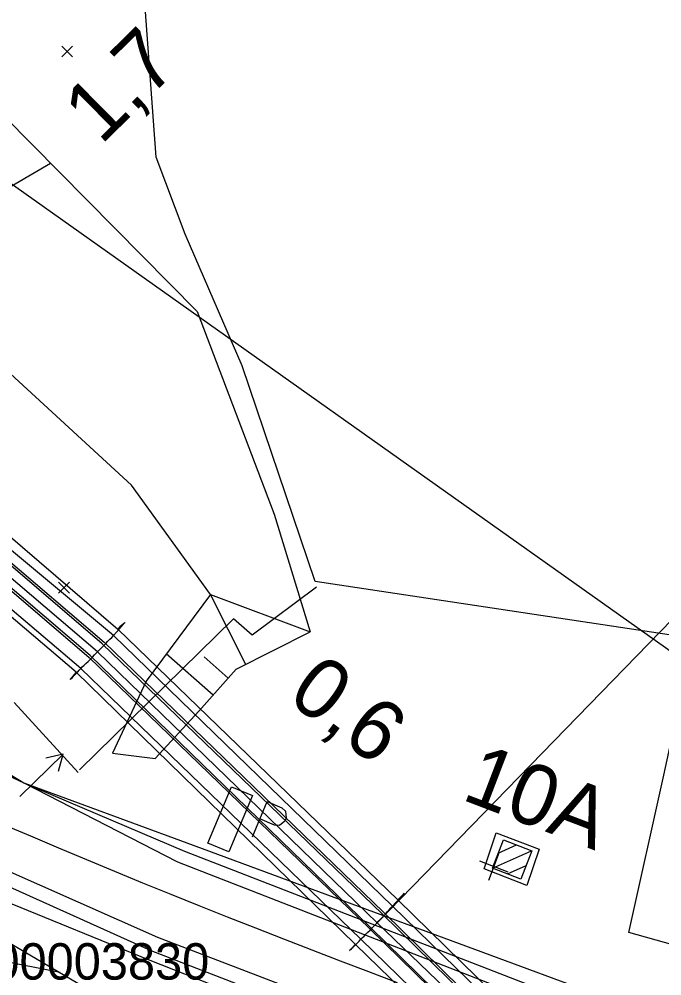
# Model space of a CAD drawing. Extents: x -800194 to -799078, y -1007177 to -1006597.
# Drawn here: x -799766.47 to -799745.3, y -1006976.93 to -1006945.41 of the extents above; entities that cross this region are included whole.
import ezdxf

# ---------------------------------------------------------------- set-up
doc = ezdxf.new("R2010")
doc.units = 0
for name, color, linetype in [('02_Osa_koleje', 7, 'Continuous'), ('Vrstva 11', 7, 'Continuous'), ('Vrstva 12', 7, 'Continuous'), ('Vrstva 13', 7, 'Continuous'), ('Vrstva 16', 7, 'Continuous'), ('Vrstva 17', 7, 'Continuous'), ('Vrstva 18', 7, 'Continuous'), ('Vrstva 36', 7, 'Continuous'), ('Vrstva 4', 7, 'Continuous'), ('Vrstva 48', 7, 'Continuous'), ('Vrstva 49', 7, 'Continuous'), ('Vrstva 55', 7, 'Continuous'), ('Vrstva 60', 7, 'Continuous'), ('Vrstva 63', 7, 'Continuous'), ('Vrstva 7', 7, 'Continuous')]:
    doc.layers.add(name, color=color, linetype=linetype)

msp = doc.modelspace()

# ---------------------------------------------------------------- linework, layer by layer
at = {"layer": '02_Osa_koleje'}
msp.add_lwpolyline([(-799770.682, -1006970.328), (-799769.768, -1006970.733), (-799768.852, -1006971.134), (-799767.934, -1006971.532), (-799767.016, -1006971.927), (-799766.096, -1006972.319), (-799765.175, -1006972.709), (-799764.252, -1006973.095), (-799763.329, -1006973.478), (-799762.404, -1006973.858), (-799761.478, -1006974.235), (-799760.55, -1006974.609), (-799759.621, -1006974.98), (-799758.692, -1006975.348), (-799757.761, -1006975.713), (-799756.828, -1006976.075), (-799755.895, -1006976.434), (-799754.96, -1006976.789), (-799754.025, -1006977.142)], dxfattribs=at)
at = {"layer": 'Vrstva 11'}
for p, q in [((-799750.69, -1006972.883), (-799750.087, -1006972.614)), ((-799750.88, -1006973.378), (-799749.592, -1006972.804)), ((-799750.389, -1006973.57), (-799749.778, -1006973.297))]:
    msp.add_line(p, q, dxfattribs=at)
msp.add_lwpolyline([(-799750.523, -1006972.447), (-799749.589, -1006972.805), (-799749.947, -1006973.739), (-799750.881, -1006973.381)], close=True, dxfattribs=at)
at = {"layer": 'Vrstva 12'}
msp.add_lwpolyline([(-799751.16, -1006973.407), (-799750.766, -1006972.211), (-799749.342, -1006972.749), (-799749.756, -1006973.956), (-799751.16, -1006973.407)], dxfattribs=at)
at = {"layer": 'Vrstva 13'}
msp.add_line((-799766.453, -1006971.023), (-799765.026, -1006969.623), dxfattribs=at)
msp.add_lwpolyline([(-799765.172, -1006970.187), (-799765.026, -1006969.623), (-799765.593, -1006969.759)], dxfattribs=at)
at = {"layer": 'Vrstva 16'}
for points in [[(-799726.857, -1006999.659), (-799736.574, -1006991.623), (-799742.439, -1006986.725), (-799754.518, -1006974.879), (-799763.734, -1006965.993), (-799777.293, -1006954.374), (-799779.945, -1006952.099), (-799783.722, -1006948.693)], [(-799783.708, -1006948.669), (-799779.9, -1006952.065), (-799777.252, -1006954.333), (-799763.672, -1006965.935), (-799754.476, -1006974.829), (-799742.393, -1006986.703), (-799736.524, -1006991.578), (-799726.778, -1006999.642)], [(-799784.356, -1006949.5), (-799780.347, -1006952.62), (-799777.716, -1006954.827), (-799764.168, -1006966.436), (-799754.935, -1006975.363), (-799742.857, -1006987.188), (-799736.94, -1006992.081), (-799727.324, -1007000.028)], [(-799727.258, -1006999.988), (-799736.887, -1006992.032), (-799742.859, -1006987.132), (-799754.894, -1006975.337), (-799764.135, -1006966.374), (-799777.698, -1006954.783), (-799780.331, -1006952.581), (-799784.321, -1006949.462)], [(-799779.465, -1006951.506), (-799778.251, -1006952.583), (-799776.738, -1006953.884), (-799763.224, -1006965.504), (-799753.999, -1006974.421), (-799741.964, -1006986.204), (-799736.168, -1006991.012), (-799728.577, -1006997.215), (-799726.123, -1006999.163)], [(-799727.952, -1007000.326), (-799729.82, -1006998.717), (-799737.37, -1006992.486), (-799743.358, -1006987.594), (-799755.401, -1006975.883), (-799764.592, -1006966.926), (-799778.073, -1006955.449), (-799779.598, -1006954.142), (-799780.843, -1006953.125)]]:
    msp.add_lwpolyline(points, dxfattribs=at)
at = {"layer": 'Vrstva 17'}
msp.add_line((-799766.63, -1006967.927), (-799764.528, -1006970.233), dxfattribs=at)
for points in [[(-799756.721, -1006963.941), (-799759.125, -1006956.836), (-799761.008, -1006952.49), (-799761.962, -1006949.962), (-799762.434, -1006943.507)], [(-799756.678, -1006964.125), (-799758.792, -1006965.704), (-799759.415, -1006965.167), (-799764.485, -1006970.145)], [(-799726.806, -1006975.491), (-799728.174, -1006980.607), (-799746.39, -1006975.498), (-799745.242, -1006970.318), (-799744.263, -1006965.815), (-799756.721, -1006963.941)]]:
    msp.add_lwpolyline(points, dxfattribs=at)
at = {"layer": 'Vrstva 18'}
msp.add_line((-799754.68, -1006975.182), (-799715.262, -1006934.616), dxfattribs=at)
for points in [[(-799776.738, -1006953.884), (-799763.224, -1006965.504), (-799753.999, -1006974.421), (-799741.964, -1006986.204), (-799736.168, -1006991.012)], [(-799728.689, -1006997.417), (-799736.272, -1006991.186), (-799742.111, -1006986.385), (-799754.178, -1006974.631), (-799763.368, -1006965.72), (-799777.061, -1006954.31)], [(-799736.701, -1006991.694), (-799742.573, -1006986.82), (-799754.68, -1006975.182), (-799763.887, -1006966.256), (-799777.391, -1006954.732)], [(-799737.37, -1006992.486), (-799743.358, -1006987.594), (-799755.401, -1006975.883), (-799764.592, -1006966.926), (-799778.073, -1006955.449)], [(-799729.664, -1006998.596), (-799737.245, -1006992.341), (-799743.186, -1006987.438), (-799755.222, -1006975.72), (-799764.444, -1006966.802), (-799777.959, -1006955.323)]]:
    msp.add_lwpolyline(points, dxfattribs=at)
for centre, major_axis, ratio, start_param, end_param in [((-799764.209, -1006966.632), (1.225, 1.347), 0.00569, 5.462132, 6.45682), ((-799764.267, -1006966.931), (1.309, 1.64), 0.066438, 0.193143, 0.570602), ((-799763.899, -1006966.226), (0.719, 0.725), 0.028964, 3.823595, 5.514697), ((-799763.469, -1006965.755), (-1.321, -1.405), 0.014987, 5.711575, 6.53997), ((-799763.588, -1006965.716), (-1.214, -1.448), 0.032329, 0.280391, 0.750862), ((-799755.015, -1006975.474), (1.23, 1.269), 0.011168, 5.449588, 6.468473), ((-799755.131, -1006975.736), (1.35, 1.533), 0.01765, 0.183735, 0.556082), ((-799754.712, -1006975.133), (0.699, 0.732), 0.056068, 3.837002, 5.520083), ((-799754.595, -1006974.816), (0.979, 1.241), 0.059951, 3.363928, 3.944453), ((-799754.422, -1006974.757), (-1.164, -1.342), 0.001186, 5.709743, 6.582824)]:
    msp.add_ellipse(centre, major_axis=major_axis, ratio=ratio, start_param=start_param, end_param=end_param, dxfattribs=at)
at = {"layer": 'Vrstva 36'}
msp.add_lwpolyline([(-799759.474, -1006970.701), (-799758.787, -1006970.989), (-799759.566, -1006972.847), (-799760.253, -1006972.559)], close=True, dxfattribs=at)
msp.add_lwpolyline([(-799758.789, -1006972.343), (-799758.304, -1006971.186), (-799757.823, -1006971.388), (-799757.698, -1006971.497), (-799757.674, -1006971.727), (-799757.717, -1006971.829), (-799757.899, -1006971.978), (-799758.062, -1006971.959), (-799758.543, -1006971.757)], dxfattribs=at)
at = {"layer": 'Vrstva 4'}
for points in [[(-799766.319, -1006970.565), (-799760.949, -1006972.542), (-799747.638, -1006977.46), (-799730.549, -1006982.982), (-799710.066, -1006987.578), (-799704.728, -1006988.346), (-799693.001, -1006990.373), (-799682.434, -1006991.64), (-799671.27, -1006992.619), (-799659.31, -1006993.026), (-799648.69, -1006993.125), (-799637.398, -1006992.704), (-799625.913, -1006992.175), (-799614.965, -1006990.831), (-799603.911, -1006989.312), (-799592.728, -1006987.172), (-799581.605, -1006984.547), (-799570.583, -1006981.598), (-799559.909, -1006978.216), (-799542.956, -1006972.25), (-799531.79, -1006967.658), (-799521.285, -1006962.191), (-799511.236, -1006957.129)], [(-799779.678, -1006964.304), (-799766.319, -1006970.565), (-799761.253, -1006973.176), (-799747.77, -1006978.421), (-799730.774, -1006983.8), (-799710.333, -1006988.709), (-799704.916, -1006989.741), (-799693.131, -1006991.407), (-799682.585, -1006992.929), (-799671.325, -1006993.879), (-799659.363, -1006994.45), (-799648.66, -1006994.501), (-799637.23, -1006994.127), (-799626.066, -1006993.335), (-799614.788, -1006992.17), (-799603.669, -1006990.506), (-799592.467, -1006988.452), (-799581.281, -1006985.916), (-799570.22, -1006982.998), (-799559.296, -1006979.606), (-799542.375, -1006973.485), (-799531.236, -1006968.774), (-799520.48, -1006963.762), (-799510.394, -1006958.536)], [(-799776.864, -1006969.085), (-799770.965, -1006971.646), (-799761.91, -1006975.649), (-799748.544, -1006980.777), (-799731.457, -1006986.215), (-799711.132, -1006991.054), (-799705.482, -1006992.16), (-799693.53, -1006994.084), (-799682.801, -1006995.384), (-799671.514, -1006996.319), (-799659.449, -1006996.851), (-799648.588, -1006996.949), (-799637.262, -1006996.573), (-799625.835, -1006995.773), (-799614.546, -1006994.586), (-799603.199, -1006992.945), (-799591.969, -1006990.857), (-799580.647, -1006988.335), (-799569.534, -1006985.311), (-799558.557, -1006981.947), (-799541.405, -1006975.739), (-799530.263, -1006971.071), (-799519.455, -1006966), (-799509.248, -1006960.724)], [(-799776.864, -1006969.085), (-799771.262, -1006971.982), (-799762.131, -1006976.093), (-799748.706, -1006981.286), (-799731.51, -1006986.353), (-799711.222, -1006991.459), (-799705.527, -1006992.587), (-799693.582, -1006994.543), (-799682.85, -1006995.904), (-799671.5, -1006996.805), (-799659.556, -1006997.356), (-799648.616, -1006997.341), (-799637.276, -1006997.071), (-799625.828, -1006996.297), (-799614.43, -1006995.109), (-799603.18, -1006993.475), (-799591.849, -1006991.264), (-799580.564, -1006988.698), (-799569.449, -1006985.746), (-799558.385, -1006982.386), (-799541.268, -1006976.227), (-799530.102, -1006971.505), (-799519.398, -1006966.36), (-799509.087, -1006961.127)], [(-799779.011, -1006963.023), (-799770.632, -1006967.944), (-799766.319, -1006970.565), (-799761.021, -1006972.82), (-799747.748, -1006977.966), (-799730.719, -1006983.271), (-799710.195, -1006988.108), (-799704.765, -1006989.181), (-799693.072, -1006990.965), (-799682.554, -1006992.238), (-799671.266, -1006993.222), (-799659.388, -1006993.765), (-799648.658, -1006993.824), (-799637.385, -1006993.531), (-799625.769, -1006992.728), (-799614.9, -1006991.542), (-799603.91, -1006989.963), (-799592.572, -1006987.892), (-799581.421, -1006985.419), (-799570.327, -1006982.332), (-799559.429, -1006979.066), (-799542.601, -1006973.013), (-799531.454, -1006968.25), (-799520.744, -1006963.214)], [(-799776.864, -1006969.085), (-799771.693, -1006972.522), (-799762.217, -1006976.394), (-799748.898, -1006981.647), (-799733.68, -1006986.66), (-799728.795, -1006987.945), (-799711.349, -1006992.599), (-799705.744, -1006994.116), (-799693.689, -1006996.09), (-799689.347, -1006996.226), (-799688.222, -1006996.296), (-799683.105, -1006997.407), (-799671.667, -1006998.275)]]:
    msp.add_lwpolyline(points, dxfattribs=at)
at = {"layer": 'Vrstva 48'}
for p, q in [((-799770.541, -1006953.137), (-799765.435, -1006950.154)), ((-799759.008, -1006966.666), (-799760.173, -1006964.364)), ((-799760.084, -1006967.683), (-799761.624, -1006966.32)), ((-799759.587, -1006967.122), (-799760.381, -1006966.419))]:
    msp.add_line(p, q, dxfattribs=at)
at = {"layer": 'Vrstva 49'}
for p, q in [((-799765.068, -1006946.299), (-799764.714, -1006946.653)), ((-799765.068, -1006946.653), (-799764.714, -1006946.299)), ((-799765.172, -1006963.963), (-799764.818, -1006964.317)), ((-799765.172, -1006964.317), (-799764.818, -1006963.963)), ((-799760.173, -1006964.364), (-799756.886, -1006965.592))]:
    msp.add_line(p, q, dxfattribs=at)
for points in [[(-799777.554, -1006942.387), (-799773.745, -1006944.786), (-799766.953, -1006948.615), (-799760.613, -1006955.042), (-799758.076, -1006961.72), (-799756.886, -1006965.592)], [(-799760.173, -1006964.364), (-799762.769, -1006960.758), (-799769.93, -1006954.183), (-799773.856, -1006947.464), (-799779.16, -1006943.327)], [(-799760.173, -1006964.364), (-799762.289, -1006967.216), (-799763.402, -1006969.589)], [(-799763.402, -1006969.589), (-799761.992, -1006969.771), (-799760.55, -1006968.21), (-799759.325, -1006966.826), (-799756.886, -1006965.592)]]:
    msp.add_lwpolyline(points, dxfattribs=at)
at = {"layer": 'Vrstva 55'}
msp.add_line((-799785.23, -1006937.71), (-799741.57, -1006968.68), dxfattribs=at)
msp.add_lwpolyline([(-799785.23, -1006937.71), (-799791.69, -1006959.99), (-799791.97, -1006960.97), (-799746.76, -1006987.67), (-799745.68, -1006988.03), (-799733.28, -1006992.13)], dxfattribs=at)
at = {"layer": 'Vrstva 63'}
msp.add_line((-799770.028, -1006975.851), (-799765.12, -1006976.804), dxfattribs=at)
at = {"layer": 'Vrstva 7'}
for p, q in [((-799750.66, -1006972.855), (-799751.018, -1006973.789)), ((-799751.306, -1006973.143), (-799750.372, -1006973.501))]:
    msp.add_line(p, q, dxfattribs=at)

# ---------------------------------------------------------------- texts
at = {"layer": 'Vrstva 11'}
msp.add_text('10A', height=2, rotation=339.0461, dxfattribs=at).set_placement((-799751.944, -1006971.101))
at = {"layer": 'Vrstva 48'}
for s, rotation, p in [('1,7', 44.6096, (-799763.776, -1006949.581)), ('0,6', 323.427, (-799757.699, -1006967.832))]:
    msp.add_text(s, height=2, rotation=rotation, dxfattribs=at).set_placement(p)
at = {"layer": 'Vrstva 60'}
msp.add_text('10100003830', height=1.2, dxfattribs=at).set_placement((-799770.028, -1006977.051))
at = {"layer": 'Vrstva 63'}
msp.add_text('(TÚ 0101)', height=2.4, rotation=142.0391, dxfattribs=at).set_placement((-799761.816, -1006984.928))

doc.saveas('drawing.dxf')
